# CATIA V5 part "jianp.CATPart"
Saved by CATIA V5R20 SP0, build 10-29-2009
Part number: 键盘
Bounding box of the stored display mesh (mm): x -50 to 50, y -35 to 37, z -2 to 2
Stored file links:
  C:\Users\GBH\Desktop\电脑\jianp.CATPart
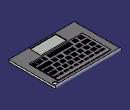
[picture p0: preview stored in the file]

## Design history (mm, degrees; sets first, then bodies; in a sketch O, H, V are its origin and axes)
Body1 (main body)
  Sketch1 on xy-plane, origin (0, 0, 0), H (1, 0, 0), V (0, 1, 0)
    line L1 (50, 35) -> (50, -35)
    line L2 (50, -35) -> (-50, -35)
    line L3 (-50, -35) -> (-50, 35)
    line L4 (-50, 35) -> (50, 35)
    length L4 = 100
    length L3 = 70
    vertical: L1 V, L3 V
    horizontal: L2 H, L4 H
    equidistance: L1 L3 O, L2 L4 O
  Pad1: profile Sketch1, direction (0, 0, 1), length 2, mirrored extent
  Sketch2 on end face of Pad1, origin (0, 0, 2), H (1, 0, 0), V (0, 1, 0)
    line L1 (-20.2047, -14.7529) -> (20.4484, -14.7529)
    line L2 (20.4484, -14.7529) -> (20.4484, -33.1456)
    line L3 (20.4484, -33.1456) -> (-20.2047, -33.1456)
    line L4 (-20.2047, -33.1456) -> (-20.2047, -14.7529)
    line L5 (-36.5385, 25.6747) -> (-30.5494, 25.6747)
    line L6 (-30.5494, 25.6747) -> (-30.5494, 22.9431)
    line L7 (-30.5494, 22.9431) -> (-36.5385, 22.9431)
    line L8 (-36.5385, 22.9431) -> (-36.5385, 25.6747)
    point P9 (-28.7346, 25.6747)
    line L9 (-28.7346, 25.6747) -> (-22.7455, 25.6747)
    line L10 (-22.7455, 25.6747) -> (-22.7455, 22.9431)
    line L11 (-22.7455, 22.9431) -> (-28.7346, 22.9431)
    line L12 (-28.7346, 22.9431) -> (-28.7346, 25.6747)
    point P11 (-22.7455, 22.9431)
    point P13 (-20.2047, 25.6747)
    line L13 (-20.2047, 25.6747) -> (-14.4362, 25.6747)
    line L14 (-14.4362, 25.6747) -> (-14.4362, 22.9431)
    line L15 (-14.4362, 22.9431) -> (-20.2047, 22.9431)
    line L16 (-20.2047, 22.9431) -> (-20.2047, 25.6747)
    point P15 (-14.4362, 22.9431)
    point P17 (-12.248, 25.6747)
    line L17 (-12.248, 25.6747) -> (-6.9597, 25.6747)
    line L18 (-6.9597, 25.6747) -> (-6.9597, 22.9431)
    line L19 (-6.9597, 22.9431) -> (-12.248, 22.9431)
    line L20 (-12.248, 22.9431) -> (-12.248, 25.6747)
    point P19 (-6.9597, 22.9431)
    point P21 (-4.4068, 25.6747)
    line L21 (-4.4068, 25.6747) -> (1.4285, 25.6747)
    line L22 (1.4285, 25.6747) -> (1.4285, 22.9431)
    line L23 (1.4285, 22.9431) -> (-4.4068, 22.9431)
    line L24 (-4.4068, 22.9431) -> (-4.4068, 25.6747)
    point P23 (1.4285, 22.9431)
    point P25 (4.1638, 25.6747)
    line L25 (4.1638, 25.6747) -> (8.9049, 25.6747)
    line L26 (8.9049, 25.6747) -> (8.9049, 22.9431)
    line L27 (8.9049, 22.9431) -> (4.1638, 22.9431)
    line L28 (4.1638, 22.9431) -> (4.1638, 25.6747)
    point P27 (8.9049, 22.9431)
    point P29 (11.8226, 25.6747)
    line L29 (11.8226, 25.6747) -> (16.5637, 25.6747)
    line L30 (16.5637, 25.6747) -> (16.5637, 22.9431)
    line L31 (16.5637, 22.9431) -> (11.8226, 22.9431)
    line L32 (11.8226, 22.9431) -> (11.8226, 25.6747)
    point P31 (16.5637, 22.9431)
    point P33 (18.5696, 25.6747)
    line L33 (18.5696, 25.6747) -> (24.2225, 25.6747)
    line L34 (24.2225, 25.6747) -> (24.2225, 22.9431)
    line L35 (24.2225, 22.9431) -> (18.5696, 22.9431)
    line L36 (18.5696, 22.9431) -> (18.5696, 25.6747)
    point P35 (24.2225, 22.9431)
    point P37 (26.5931, 25.6747)
    line L37 (26.5931, 25.6747) -> (31.5166, 25.6747)
    line L38 (31.5166, 25.6747) -> (31.5166, 22.9431)
    line L39 (31.5166, 22.9431) -> (26.5931, 22.9431)
    line L40 (26.5931, 22.9431) -> (26.5931, 25.6747)
    point P39 (31.5166, 22.9431)
    point P41 (33.5225, 25.6747)
    line L41 (33.5225, 25.6747) -> (38.8107, 25.6747)
    line L42 (38.8107, 25.6747) -> (38.8107, 22.9431)
    line L43 (38.8107, 22.9431) -> (33.5225, 22.9431)
    line L44 (33.5225, 22.9431) -> (33.5225, 25.6747)
    point P43 (38.8107, 22.9431)
    point P45 (-36.5385, 19.6642)
    line L45 (-36.5385, 19.6642) -> (-32.8538, 19.6642)
    line L46 (-32.8538, 19.6642) -> (-32.8538, 14.7239)
    line L47 (-32.8538, 14.7239) -> (-36.5385, 14.7239)
    line L48 (-36.5385, 14.7239) -> (-36.5385, 19.6642)
    point P49 (-30.5494, 19.6642)
    line L49 (-30.5494, 19.6642) -> (-24.4656, 19.6642)
    line L50 (-24.4656, 19.6642) -> (-24.4656, 14.7239)
    line L51 (-24.4656, 14.7239) -> (-30.5494, 14.7239)
    line L52 (-30.5494, 14.7239) -> (-30.5494, 19.6642)
    point P51 (-24.4656, 14.7239)
    point P53 (-21.548, 19.6642)
    line L53 (-21.548, 19.6642) -> (-15.7127, 19.6642)
    line L54 (-15.7127, 19.6642) -> (-15.7127, 14.7239)
    line L55 (-15.7127, 14.7239) -> (-21.548, 14.7239)
    line L56 (-21.548, 14.7239) -> (-21.548, 19.6642)
    point P55 (-15.7127, 14.7239)
    point P57 (-12.248, 19.6642)
    line L57 (-12.248, 19.6642) -> (-6.9597, 19.6642)
    line L58 (-6.9597, 19.6642) -> (-6.9597, 14.7239)
    line L59 (-6.9597, 14.7239) -> (-12.248, 14.7239)
    line L60 (-12.248, 14.7239) -> (-12.248, 19.6642)
    point P59 (-6.9597, 14.7239)
    point P61 (-4.4068, 19.6642)
    line L61 (-4.4068, 19.6642) -> (1.4285, 19.6642)
    line L62 (1.4285, 19.6642) -> (1.4285, 14.7239)
    line L63 (1.4285, 14.7239) -> (-4.4068, 14.7239)
    line L64 (-4.4068, 14.7239) -> (-4.4068, 19.6642)
    point P63 (1.4285, 14.7239)
    point P65 (4.1638, 19.6642)
    line L65 (4.1638, 19.6642) -> (9.999, 19.6642)
    line L66 (9.999, 19.6642) -> (9.999, 14.7239)
    line L67 (9.999, 14.7239) -> (4.1638, 14.7239)
    line L68 (4.1638, 14.7239) -> (4.1638, 19.6642)
    point P67 (9.999, 14.7239)
    point P69 (12.9167, 19.6642)
    line L69 (12.9167, 19.6642) -> (18.5696, 19.6642)
    line L70 (18.5696, 19.6642) -> (18.5696, 14.7239)
    line L71 (18.5696, 14.7239) -> (12.9167, 14.7239)
    line L72 (12.9167, 14.7239) -> (12.9167, 19.6642)
    point P71 (18.5696, 14.7239)
    point P73 (21.4873, 19.6642)
    line L73 (21.4873, 19.6642) -> (26.5931, 19.6642)
    line L74 (26.5931, 19.6642) -> (26.5931, 14.7239)
    line L75 (26.5931, 14.7239) -> (21.4873, 14.7239)
    line L76 (21.4873, 14.7239) -> (21.4873, 19.6642)
    point P75 (26.5931, 14.7239)
    point P77 (29.1461, 19.6642)
    line L77 (29.1461, 19.6642) -> (38.8107, 19.6642)
    line L78 (38.8107, 19.6642) -> (38.8107, 14.7239)
    line L79 (38.8107, 14.7239) -> (29.1461, 14.7239)
    line L80 (29.1461, 14.7239) -> (29.1461, 19.6642)
    point P79 (38.8107, 14.7239)
    point P81 (-36.5385, 12.1622)
    line L81 (-36.5385, 12.1622) -> (-30.5494, 12.1622)
    line L82 (-30.5494, 12.1622) -> (-30.5494, 6.673)
    line L83 (-30.5494, 6.673) -> (-36.5385, 6.673)
    line L84 (-36.5385, 6.673) -> (-36.5385, 12.1622)
    point P83 (-30.5494, 6.673)
    point P85 (-27.2009, 12.1622)
    line L85 (-27.2009, 12.1622) -> (-21.548, 12.1622)
    line L86 (-21.548, 12.1622) -> (-21.548, 6.673)
    line L87 (-21.548, 6.673) -> (-27.2009, 6.673)
    line L88 (-27.2009, 6.673) -> (-27.2009, 12.1622)
    point P87 (-21.548, 6.673)
    point P89 (-17.9009, 12.1622)
    line L89 (-17.9009, 12.1622) -> (-12.248, 12.1622)
    line L90 (-12.248, 12.1622) -> (-12.248, 6.673)
    line L91 (-12.248, 6.673) -> (-17.9009, 6.673)
    line L92 (-17.9009, 6.673) -> (-17.9009, 12.1622)
    point P91 (-12.248, 6.673)
    point P93 (-8.7833, 12.1622)
    line L93 (-8.7833, 12.1622) -> (-2.7656, 12.1622)
    line L94 (-2.7656, 12.1622) -> (-2.7656, 6.673)
    line L95 (-2.7656, 6.673) -> (-8.7833, 6.673)
    line L96 (-8.7833, 6.673) -> (-8.7833, 12.1622)
    point P95 (-2.7656, 6.673)
    point P97 (0, 12.1622)
    line L97 (0, 12.1622) -> (5.8049, 12.1622)
    line L98 (5.8049, 12.1622) -> (5.8049, 6.673)
    line L99 (5.8049, 6.673) -> (0, 6.673)
    line L100 (0, 6.673) -> (0, 12.1622)
    point P99 (5.8049, 6.673)
    point P101 (8.9049, 12.1622)
    line L101 (8.9049, 12.1622) -> (14.7402, 12.1622)
    line L102 (14.7402, 12.1622) -> (14.7402, 6.673)
    line L103 (14.7402, 6.673) -> (8.9049, 6.673)
    line L104 (8.9049, 6.673) -> (8.9049, 12.1622)
    point P103 (14.7402, 6.673)
    point P105 (17.6579, 12.1622)
    line L105 (17.6579, 12.1622) -> (24.2225, 12.1622)
    line L106 (24.2225, 12.1622) -> (24.2225, 6.673)
    line L107 (24.2225, 6.673) -> (17.6579, 6.673)
    line L108 (17.6579, 6.673) -> (17.6579, 12.1622)
    point P107 (24.2225, 6.673)
    point P109 (27.8696, 12.1622)
    line L109 (27.8696, 12.1622) -> (38.8107, 12.1622)
    line L110 (38.8107, 12.1622) -> (38.8107, 6.673)
    line L111 (38.8107, 6.673) -> (27.8696, 6.673)
    line L112 (27.8696, 6.673) -> (27.8696, 12.1622)
    point P111 (38.8107, 6.673)
    point P113 (-36.5385, 3.9284)
    line L113 (-36.5385, 3.9284) -> (-27.2009, 3.9284)
    line L114 (-27.2009, 3.9284) -> (-27.2009, -1.5609)
    line L115 (-27.2009, -1.5609) -> (-36.5385, -1.5609)
    line L116 (-36.5385, -1.5609) -> (-36.5385, 3.9284)
    point P115 (-27.2009, -1.5609)
    point P117 (-24.4656, 3.9284)
    line L117 (-24.4656, 3.9284) -> (-17.9009, 3.9284)
    line L118 (-17.9009, 3.9284) -> (-17.9009, -1.5609)
    line L119 (-17.9009, -1.5609) -> (-24.4656, -1.5609)
    line L120 (-24.4656, -1.5609) -> (-24.4656, 3.9284)
    point P119 (-17.9009, -1.5609)
    point P121 (-14.4362, 3.9284)
    line L121 (-14.4362, 3.9284) -> (-8.7833, 3.9284)
    line L122 (-8.7833, 3.9284) -> (-8.7833, -1.5609)
    line L123 (-8.7833, -1.5609) -> (-14.4362, -1.5609)
    line L124 (-14.4362, -1.5609) -> (-14.4362, 3.9284)
    point P123 (-8.7833, -1.5609)
    point P125 (-6.9597, 3.9284)
    line L125 (-6.9597, 3.9284) -> (0, 3.9284)
    line L126 (0, 3.9284) -> (0, -1.5609)
    line L127 (0, -1.5609) -> (-6.9597, -1.5609)
    line L128 (-6.9597, -1.5609) -> (-6.9597, 3.9284)
    point P127 (0, -1.5609)
    point P129 (4.1638, 3.9284)
    line L129 (4.1638, 3.9284) -> (9.999, 3.9284)
    line L130 (9.999, 3.9284) -> (9.999, -1.5609)
    line L131 (9.999, -1.5609) -> (4.1638, -1.5609)
    line L132 (4.1638, -1.5609) -> (4.1638, 3.9284)
    point P131 (9.999, -1.5609)
    point P133 (12.9167, 3.9284)
    line L133 (12.9167, 3.9284) -> (18.5696, 3.9284)
    line L134 (18.5696, 3.9284) -> (18.5696, -1.5609)
    line L135 (18.5696, -1.5609) -> (12.9167, -1.5609)
    line L136 (12.9167, -1.5609) -> (12.9167, 3.9284)
    point P135 (18.5696, -1.5609)
    point P137 (21.4873, 3.9284)
    line L137 (21.4873, 3.9284) -> (38.8107, 3.9284)
    line L138 (38.8107, 3.9284) -> (38.8107, -1.5609)
    line L139 (38.8107, -1.5609) -> (21.4873, -1.5609)
    line L140 (21.4873, -1.5609) -> (21.4873, 3.9284)
    point P139 (38.8107, -1.5609)
    point P141 (-36.5385, -4.8544)
    line L141 (-36.5385, -4.8544) -> (-30.5494, -4.8544)
    line L142 (-30.5494, -4.8544) -> (-30.5494, -10.7096)
    line L143 (-30.5494, -10.7096) -> (-36.5385, -10.7096)
    line L144 (-36.5385, -10.7096) -> (-36.5385, -4.8544)
    point P143 (-30.5494, -10.7096)
    point P145 (-27.2009, -4.8544)
    line L145 (-27.2009, -4.8544) -> (-21.548, -4.8544)
    line L146 (-21.548, -4.8544) -> (-21.548, -10.7096)
    line L147 (-21.548, -10.7096) -> (-27.2009, -10.7096)
    line L148 (-27.2009, -10.7096) -> (-27.2009, -4.8544)
    point P147 (-21.548, -10.7096)
    point P149 (-17.9009, -4.8544)
    line L149 (-17.9009, -4.8544) -> (16.5637, -4.8544)
    line L150 (16.5637, -4.8544) -> (16.5637, -10.7096)
    line L151 (16.5637, -10.7096) -> (-17.9009, -10.7096)
    line L152 (-17.9009, -10.7096) -> (-17.9009, -4.8544)
    point P151 (16.5637, -10.7096)
    point P153 (20.4484, -4.8544)
    line L153 (20.4484, -4.8544) -> (24.2225, -4.8544)
    line L154 (24.2225, -4.8544) -> (24.2225, -10.7096)
    line L155 (24.2225, -10.7096) -> (20.4484, -10.7096)
    line L156 (20.4484, -10.7096) -> (20.4484, -4.8544)
    point P155 (24.2225, -10.7096)
    point P157 (26.5931, -4.8544)
    line L157 (26.5931, -4.8544) -> (33.5225, -4.8544)
    line L158 (33.5225, -4.8544) -> (33.5225, -7.599)
    line L159 (33.5225, -7.599) -> (26.5931, -7.599)
    line L160 (26.5931, -7.599) -> (26.5931, -4.8544)
    point P159 (33.5225, -7.599)
    point P161 (26.5931, -8.5139)
    line L161 (26.5931, -8.5139) -> (33.5225, -8.5139)
    line L162 (33.5225, -8.5139) -> (33.5225, -10.7096)
    line L163 (33.5225, -10.7096) -> (26.5931, -10.7096)
    line L164 (26.5931, -10.7096) -> (26.5931, -8.5139)
    point P163 (33.5225, -10.7096)
    point P165 (35.346, -4.8544)
    line L165 (35.346, -4.8544) -> (38.8107, -4.8544)
    line L166 (38.8107, -4.8544) -> (38.8107, -10.7096)
    line L167 (38.8107, -10.7096) -> (35.346, -10.7096)
    line L168 (35.346, -10.7096) -> (35.346, -4.8544)
    point P167 (38.8107, -10.7096)
    horizontal: L1 H, L3 H, L5 H, L7 H, L9 H, L11 H, L13 H, L15 H, L17 H, L19 H, L21 H, L23 H, L25 H, L27 H, L29 H, L31 H, L33 H, L35 H, L37 H, L39 H, L41 H, L43 H, L45 H, L47 H, L49 H, L51 H, L53 H, L55 H, L57 H, L59 H, L61 H, L63 H, L65 H, L67 H, L69 H, L71 H, L73 H, L75 H, L77 H, L79 H, L81 H, L83 H, L85 H, L87 H, L89 H, L91 H, L93 H, L95 H, L97 H, L99 H, L101 H, L103 H, L105 H, L107 H, L109 H, L111 H, L113 H, L115 H, L117 H, L119 H, L121 H, L123 H, L125 H, L127 H, L129 H, L131 H, L133 H, L135 H, L137 H, L139 H, L141 H, L143 H, L145 H, L147 H, L149 H, L151 H, L153 H, L155 H, L157 H, L159 H, L161 H, L163 H, L165 H, L167 H
    vertical: L2 V, L4 V, L6 V, L8 V, L10 V, L12 V, L14 V, L16 V, L18 V, L20 V, L22 V, L24 V, L26 V, L28 V, L30 V, L32 V, L34 V, L36 V, L38 V, L40 V, L42 V, L44 V, L46 V, L48 V, L50 V, L52 V, L54 V, L56 V, L58 V, L60 V, L62 V, L64 V, L66 V, L68 V, L70 V, L72 V, L74 V, L76 V, L78 V, L80 V, L82 V, L84 V, L86 V, L88 V, L90 V, L92 V, L94 V, L96 V, L98 V, L100 V, L102 V, L104 V, L106 V, L108 V, L110 V, L112 V, L114 V, L116 V, L118 V, L120 V, L122 V, L124 V, L126 V, L128 V, L130 V, L132 V, L134 V, L136 V, L138 V, L140 V, L142 V, L144 V, L146 V, L148 V, L150 V, L152 V, L154 V, L156 V, L158 V, L160 V, L162 V, L164 V, L166 V, L168 V
    coincidence: P9 L5, P11 L7, P13 L5, P13 L4, P15 L7, P17 L5, P19 L7, P21 L5, P23 L7, P25 L5, P27 L7, P29 L5, P31 L7, P33 L5, P35 L7, P37 L5, P39 L7, P41 L5, P43 L7, P45 L8, P49 L45, P49 L6, P51 L47, P53 L45, P55 L47, P57 L45, P57 L20, P59 L47, P59 L18, P61 L45, P61 L24, P63 L47, P63 L22, P65 L45, P65 L28, P67 L47, P69 L45, P71 L47, P71 L36, P73 L45, P75 L47, P75 L40, P77 L45, P79 L47, P79 L42, P81 L8, P83 L6, P85 L81, P87 L83, P87 L56, P89 L81, P91 L83, P91 L20, P93 L81, P95 L83, P97 L81, P97 V, P99 L83, P101 L81, P101 L26, P103 L83, P105 L81, P107 L83, P107 L34, P109 L81, P111 L83, P111 L42, P113 L8, P115 L88, P117 L113, P117 L50, P119 L115, P119 L92, P121 L113, P121 L14, P123 L115, P123 L96, P125 L113, P125 L18, P127 L115, P127 V, P129 L113, P129 L28, P131 L115, P131 L66, P133 L113, P133 L72, P135 L115, P135 L36, P137 L113, P137 L76, P139 L115, P139 L42, P141 L8, P143 L6, P145 L141, P145 L88, P147 L143, P147 L56, P149 L141, P149 L92, P151 L143, P151 L30, P153 L141, P153 L2, P155 L143, P155 L34, P157 L141, P157 L40, P159 L44, P161 L40, P163 L158, P163 L143, P165 L141, P167 L143, P167 L42
  Pocket1: profile Sketch2, direction (0, 0, -1), length 1
  Sketch3 on end face of Pad1, origin (0, 0, 2), H (1, 0, 0), V (0, 1, 0)
    line L1 (-40.1479, -12.7223) -> (40.0872, -12.7223)
    line L2 (40.0872, -12.7223) -> (40.0872, 30.6427)
    line L3 (40.0872, 30.6427) -> (-40.1479, 30.6427)
    line L4 (-40.1479, 30.6427) -> (-40.1479, -12.7223)
    horizontal: L1 H, L3 H
    vertical: L2 V, L4 V
  Pocket2: profile Sketch3, direction (0, 0, -1), length 1, outer side
  Sketch4 on face of Pocket2, origin (0, 0, 1), H (1, 0, 0), V (0, 1, 0)
    line L1 (-19.9677, -15.9144) -> (19.7441, -15.9144)
    line L2 (19.7441, -15.9144) -> (19.7441, -33.0205)
    line L3 (19.7441, -33.0205) -> (-19.9677, -33.0205)
    line L4 (-19.9677, -33.0205) -> (-19.9677, -15.9144)
    circle A1 centre (45.2158, 31.3792) radius 3.0691
    horizontal: L1 H, L3 H
    vertical: L2 V, L4 V
  Pocket3: profile Sketch4, direction (0, 0, -1), length 1
  Sketch5 on face of Pad1 from Sketch1.L1, origin (50, 0, 0), H (0, 1, 0), V (0, 0, 1)
    line L1 (35, 2) -> (35, -2)
    point P3 (-35, -2)
    point P4 (-35, 2)
    arc A1 centre (35, 0) radius 2 from (35, -2) to (35, 2) ccw
    radius A1 = 2
    vertical: L1 V
  Pad2: profile Sketch5, direction (-1, 0, 0), length 100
